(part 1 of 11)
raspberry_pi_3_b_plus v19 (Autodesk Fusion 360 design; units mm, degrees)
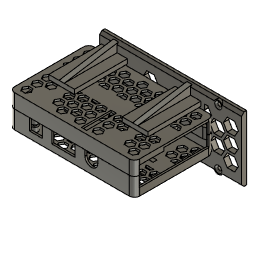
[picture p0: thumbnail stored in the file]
parameter "muc_width_int" = 6.9
parameter "muc_width_ext" = 7.5
parameter "muc_depth" = 5
parameter "muc_height_int" = 1.85
parameter "muc_height_ext" = 2.45
parameter "muc_shell_thickness" = 0.3
parameter "sdc_width" = 12
parameter "sdc_length" = 11.4
parameter "sdc_height" = 1.42
parameter "sdc_shell_thickness" = 0.15
parameter "h20x2_spacing" = 2.54
parameter "h20x2_pin_size" = 0.635
parameter "h20x2_pin_height" = 10
parameter "h20x2_pin_descent" = 3
parameter "h20x2_spacer_leg_size" = 0.5
parameter "h20x2_spacer_leg_height" = 0.5
parameter "h20x2_spacer_height" = 2.54
parameter "h20x2_spacer_taper" = 25
parameter "h20x2_spacer_break_depth" = 0.15
parameter "sop3_1_lead_thickness" = 0.1
parameter "sop3_1_lead_attach" = 0.3
parameter "sop3_1_lead_width" = 0.2
parameter "sop3_1_lead_spacing" = 0.5
parameter "sop3_1_package_width" = 1.6
parameter "sop3_1_package_height" = 0.6
parameter "sop3_1_package_depth" = 0.75
parameter "sop3_1_above_board" = 0.05
parameter "sop3_1_lead_extension" = 0.4
parameter "sop3_1_lead_foot_angle" = 5
parameter "sop3_1_lead_into_package" = 0.15
parameter "sop3_1_optional_lead_extension" = 0
parameter "cap0402_height" = 0.5
parameter "cap0402_width" = 0.5
parameter "cap0402_length" = 1
parameter "cap0402_tin_len" = 0.2
parameter "cap0402_tin_thick_radial" = 0.02
parameter "cap0402_tin_thick_axial" = 0.06
parameter "cap0402_land_spacing" = 0.5
parameter "cap0402_land_width" = 0.6
parameter "cap0402_land_length" = 0.5
parameter "cap0402_height_1" = 0.5
parameter "cap0402_width_1" = 0.5
parameter "cap0402_length_1" = 1
parameter "cap0402_tin_len_1" = 0.2
parameter "cap0402_tin_thick_radial_1" = 0.02
parameter "cap0402_tin_thick_axial_1" = 0.06
parameter "cap0402_land_spacing_1" = 0.5
parameter "cap0402_land_width_1" = 0.6
parameter "cap0402_land_length_1" = 0.5
parameter "h2x2_spacing" = 2.54
parameter "h2x2_pin_size" = 0.635
parameter "h2x2_pin_height" = 10
parameter "h2x2_pin_descent" = 3
parameter "h2x2_spacer_leg_size" = 0.5
parameter "h2x2_spacer_leg_height" = 0.5
parameter "h2x2_spacer_height" = 2.54
parameter "h2x2_spacer_taper" = 25
parameter "h2x2_spacer_break_depth" = 0.15
parameter "pj322_package_width" = 7
parameter "pj322_package_length" = 15
parameter "pj322_package_height" = 6
parameter "pj322_above_board" = 0.01
parameter "d372" = 0.5
canvas "Canvas1"
sketch "Sketch1" plane through (0, 0, 0) normal (0, 0, 1) x axis (1, 0, 0)
  line L1 (39.4, 28) -> (-39.4, 28)
  line L2 (39.4, 27.9) -> (39.4, 28)
  line L3 (42.5, 24.9) -> (42.4, 24.9)
  line L4 (42.5, -24.9) -> (42.5, 24.9)
  line L5 (42.4, -24.9) -> (42.5, -24.9)
  line L6 (39.4, -28) -> (39.4, -27.9)
  line L7 (-39.4, -28) -> (39.4, -28)
  line L8 (-39.4, -27.9) -> (-39.4, -28)
  line L9 (-42.5, -24.9) -> (-42.4, -24.9)
  line L10 (-42.5, 24.9) -> (-42.5, -24.9)
  line L11 (-42.4, 24.9) -> (-42.5, 24.9)
  line L12 (-39.4, 28) -> (-39.4, 27.9)
  line L13 (39.4, 24.9) -> (-39.4, -24.9)
  line L14 (39.4, -24.9) -> (-39.4, 24.9)
  line L15 (-17.625, -29.5) -> (-3.375, -29.5)
  line L16 (-17.625, -17.5) -> (-17.625, -29.5)
  line L17 (-3.375, -17.5) -> (-17.625, -17.5)
  line L18 (-3.375, -29.5) -> (-3.375, -17.5)
  line L19 (-17.625, -17.5) -> (-3.375, -29.5)
  line L20 (-3.375, -17.5) -> (-17.625, -29.5)
  line L21 (23.375, -25.5) -> (44.625, -25.5)
  line L22 (23.375, -10) -> (23.375, -25.5)
  line L23 (44.625, -10) -> (23.375, -10)
  line L24 (44.625, -25.5) -> (44.625, -10)
  line L25 (23.375, -10) -> (44.625, -25.5)
  line L26 (44.625, -10) -> (23.375, -25.5)
  line L27 (26.75, -5.625) -> (44.25, -5.625)
  line L28 (26.75, 7.625) -> (26.75, -5.625)
  line L29 (44.25, 7.625) -> (26.75, 7.625)
  line L30 (44.25, -5.625) -> (44.25, 7.625)
  line L31 (26.75, 7.625) -> (44.25, -5.625)
  line L32 (44.25, 7.625) -> (26.75, -5.625)
  line L33 (26.75, 12.375) -> (44.25, 12.375)
  line L34 (26.75, 25.625) -> (26.75, 12.375)
  line L35 (44.25, 25.625) -> (26.75, 25.625)
  line L36 (44.25, 12.375) -> (44.25, 25.625)
  line L37 (26.75, 25.625) -> (44.25, 12.375)
  line L38 (44.25, 25.625) -> (26.75, 12.375)
  line L39 (7.5, -27.75) -> (14.5, -27.75)
  line L40 (7.5, -15.75) -> (7.5, -27.75)
  line L41 (14.5, -15.75) -> (7.5, -15.75)
  line L42 (14.5, -27.75) -> (14.5, -15.75)
  line L43 (7.5, -15.75) -> (14.5, -27.75)
  line L44 (14.5, -15.75) -> (7.5, -27.75)
  line L45 (-35.65, -29.625) -> (-28.15, -29.625)
  line L46 (-35.65, -23.375) -> (-35.65, -29.625)
  line L47 (-28.15, -23.375) -> (-35.65, -23.375)
  line L48 (-28.15, -29.625) -> (-28.15, -23.375)
  line L49 (-35.65, -23.375) -> (-28.15, -29.625)
  line L50 (-28.15, -23.375) -> (-35.65, -29.625)
  line L51 (1, -27.625) -> (4, -27.625)
  line L52 (1, -5.375) -> (1, -27.625)
  line L53 (4, -5.375) -> (1, -5.375)
  line L54 (4, -27.625) -> (4, -5.375)
  line L55 (1, -5.375) -> (4, -27.625)
  line L56 (4, -5.375) -> (1, -27.625)
  line L57 (-40, -11.125) -> (-37, -11.125)
  line L58 (-40, 11.125) -> (-40, -11.125)
  line L59 (-37, 11.125) -> (-40, 11.125)
  line L60 (-37, -11.125) -> (-37, 11.125)
  line L61 (-40, 11.125) -> (-37, -11.125)
  line L62 (-37, 11.125) -> (-40, -11.125)
  line L63 (16.5, 16.127) -> (21.5, 16.127)
  line L64 (16.5, 20.627) -> (16.5, 16.127)
  line L65 (21.5, 20.627) -> (16.5, 20.627)
  line L66 (21.5, 16.127) -> (21.5, 20.627)
  line L67 (16.5, 20.627) -> (21.5, 16.127)
  line L68 (21.5, 20.627) -> (16.5, 16.127)
  line L69 (16.5, 11.01) -> (21.5, 11.01)
  line L70 (16.5, 13.01) -> (16.5, 11.01)
  line L71 (21.5, 13.01) -> (16.5, 13.01)
  line L72 (21.5, 11.01) -> (21.5, 13.01)
  line L73 (16.5, 13.01) -> (21.5, 11.01)
  line L74 (21.5, 13.01) -> (16.5, 11.01)
  line L75 (-35.5, 21.75) -> (15.5, 21.75)
  line L76 (-35.5, 26.75) -> (-35.5, 21.75)
  line L77 (15.5, 26.75) -> (-35.5, 26.75)
  line L78 (15.5, 21.75) -> (15.5, 26.75)
  line L79 (-35.5, 26.75) -> (15.5, 21.75)
  line L80 (15.5, 26.75) -> (-35.5, 21.75)
  line L81 (20.27, 12.01) -> (17.73, 12.01)
  line L82 (20.8, 18.377) -> (19, 18.377)
  line L83 (19, 20) -> (19, 18.377)
  arc A1 centre (39.4, 24.9) radius 3 clockwise from (39.4, 27.9) to (42.4, 24.9)
  arc A2 centre (39.4, -24.9) radius 3 clockwise from (42.4, -24.9) to (39.4, -27.9)
  arc A3 centre (-39.4, -24.9) radius 3 clockwise from (-39.4, -27.9) to (-42.4, -24.9)
  arc A4 centre (-39.4, 24.9) radius 3 clockwise from (-42.4, 24.9) to (-39.4, 27.9)
  circle C1 centre (-39, 24.5) radius 1.375
  circle C2 centre (19, 24.5) radius 1.375
  circle C3 centre (19, -24.5) radius 1.375
  circle C4 centre (-39, -24.5) radius 1.375
  circle C5 centre (17.73, 12.01) radius 0.5
  circle C6 centre (20.27, 12.01) radius 0.5
  circle C7 centre (17.73, 19.647) radius 0.5
  circle C8 centre (20.27, 19.647) radius 0.5
  circle C9 centre (20.27, 17.107) radius 0.5
  circle C10 centre (17.73, 17.107) radius 0.5
  circle C11 centre (-34.13, 22.98) radius 0.5
  circle C12 centre (-31.59, 22.98) radius 0.5
  circle C13 centre (-29.05, 22.98) radius 0.5
  circle C14 centre (-26.51, 22.98) radius 0.5
  circle C15 centre (-23.97, 22.98) radius 0.5
  circle C16 centre (-21.43, 22.98) radius 0.5
  circle C17 centre (-18.89, 22.98) radius 0.5
  circle C18 centre (-16.35, 22.98) radius 0.5
  circle C19 centre (-13.81, 22.98) radius 0.5
  circle C20 centre (-11.27, 22.98) radius 0.5
  circle C21 centre (-8.73, 22.98) radius 0.5
  circle C22 centre (-6.19, 22.98) radius 0.5
  circle C23 centre (-3.65, 22.98) radius 0.5
  circle C24 centre (-1.11, 22.98) radius 0.5
  circle C25 centre (1.43, 22.98) radius 0.5
  circle C26 centre (3.97, 22.98) radius 0.5
  circle C27 centre (6.51, 22.98) radius 0.5
  circle C28 centre (9.05, 22.98) radius 0.5
  circle C29 centre (11.59, 22.98) radius 0.5
  circle C30 centre (14.13, 22.98) radius 0.5
  circle C31 centre (-34.13, 25.52) radius 0.5
  circle C32 centre (-31.59, 25.52) radius 0.5
  circle C33 centre (-29.05, 25.52) radius 0.5
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  point P21 (-39.4, 24.9)
  point P6 (39.4, 24.9)
  point P11 (39.4, -24.9)
  point P15 (-39.4, -24.9)
  point P22 (-39.4, -24.9)
  point P23 (39.4, 24.9)
  point P24 (-39.4, 24.9)
  point P25 (39.4, -24.9)
  point P26 (0, 0)
  point P1 (0, 0)
  point P27 (-39, 24.5)
  point P30 (-39, -24.5)
  point P29 (19, -24.5)
  point P28 (19, 24.5)
  point P35 (-10.5, -23.5)
  point P40 (34, -17.75)
  point P45 (35.5, 1)
  point P50 (35.5, 19)
  point P55 (11, -21.75)
  point P60 (-31.9, -26.5)
  point P65 (2.5, -16.5)
  point P70 (-38.5, 0)
  point P75 (19, 18.377)
  point P80 (19, 12.01)
  point P85 (-10, 24.25)
  point P86 (17.73, 12.01)
  point P88 (17.73, 12.01)
  point P87 (20.27, 12.01)
  point P89 (20.27, 12.01)
  point P94 (19, 18.377)
  point P90 (17.73, 19.647)
  point P91 (20.27, 19.647)
  point P93 (17.73, 17.107)
  point P92 (20.27, 17.107)
  point P2 (-39.4, 28)
  point P20 (-39.4, 27.9)
  point P18 (-42.5, 24.9)
  point P19 (-42.4, 24.9)
  point P16 (-42.4, -24.9)
  point P17 (-42.5, -24.9)
  point P13 (-39.4, -28)
  point P14 (-39.4, -27.9)
  point P10 (39.4, -27.9)
  point P12 (39.4, -28)
  point P8 (42.5, -24.9)
  point P9 (42.4, -24.9)
  point P5 (42.4, 24.9)
  point P7 (42.5, 24.9)
  point P3 (39.4, 28)
  point P4 (39.4, 27.9)
  point P97 (-34.13, 22.98)
  horizontal L1
  vertical L12
  vertical L10
  horizontal L11
  coincident L11 P21
  coincident P21 L12
  vertical L2
  coincident L2 P6
  coincident P6 L3
  horizontal L3
  vertical L4
  horizontal L5
  vertical L6
  horizontal L7
  coincident P11 L6
  coincident L5 P11
  horizontal L9
  vertical L8
  coincident P15 L9
  coincident L8 P15
  equal A1 A4
  equal A3 A4
  equal A2 A3
  coincident P15 P22
  coincident P6 P23
  coincident P21 P24
  coincident P11 P25
  midpoint L13 P26
  coincident P1 P26
  equal C2 C3
  equal C2 C4
  equal C1 C4
  vertical P27 P30
  horizontal P29 P30
  vertical P28 P29
  horizontal P27 P28
  perpendicular L15 L16
  parallel L15 L17
  parallel L16 L18
  horizontal L15
  coincident L19 P35
  coincident L20 P35
  perpendicular L21 L22
  parallel L21 L23
  parallel L22 L24
  horizontal L21
  coincident L25 P40
  coincident L26 P40
  perpendicular L27 L28
  parallel L27 L29
  parallel L28 L30
  horizontal L27
  coincident L31 P45
  coincident L32 P45
  perpendicular L33 L34
  parallel L33 L35
  parallel L34 L36
  horizontal L33
  coincident L37 P50
  coincident L38 P50
  perpendicular L39 L40
  parallel L39 L41
  parallel L40 L42
  horizontal L39
  coincident L43 P55
  coincident L44 P55
  perpendicular L45 L46
  parallel L45 L47
  parallel L46 L48
  horizontal L45
  coincident L49 P60
  coincident L50 P60
  perpendicular L51 L52
  parallel L51 L53
  parallel L52 L54
  horizontal L51
  coincident L55 P65
  coincident L56 P65
  perpendicular L57 L58
  parallel L57 L59
  parallel L58 L60
  horizontal L57
  coincident L61 P70
  coincident L62 P70
  perpendicular L63 L64
  parallel L63 L65
  parallel L64 L66
  horizontal L63
  coincident L67 P75
  coincident L68 P75
  perpendicular L69 L70
  parallel L69 L71
  parallel L70 L72
  horizontal L69
  coincident L73 P80
  coincident L74 P80
  perpendicular L75 L76
  parallel L75 L77
  parallel L76 L78
  horizontal L75
  coincident L79 P85
  coincident L80 P85
  vertical P28 P75
  vertical P28 P80
  horizontal L81
  midpoint P80 L81
  coincident P86 P88
  coincident P87 P89
  equal C5 C6
  equal C7 C10
  equal C9 C10
  equal C8 C9
  coincident P75 P94
  horizontal L82
  perpendicular L82 L83
  symmetric P90 P91 L83
  symmetric P90 P93 L82
  symmetric P91 P92 L82
  dimension "d1" distance P2 P20 = 0.1
  dimension "d2" distance P18 P19 = 0.1 (= "d1")
  dimension "d3" distance P16 P17 = 0.1 (= "d1")
  dimension "d4" distance P13 P14 = 0.1 (= "d1")
  dimension "d5" distance P10 P12 = 0.1 (= "d1")
  dimension "d6" distance P8 P9 = 0.1 (= "d1")
  dimension "d7" distance P5 P7 = 0.1 (= "d1")
  dimension "d8" distance P3 P4 = 0.1 (= "d1")
  dimension "d9" radius A1 = 3
  dimension "d10" distance L4 L10 = 85
  dimension "d11" distance L1 L7 = 56
  dimension "d12" distance L10 P27 = 3.5
  dimension "d13" distance L1 P27 = 3.5
  dimension "d14" diameter C1 = 2.75
  dimension "d15" distance P27 P28 = 58
  dimension "d16" distance P27 P30 = 49
  dimension "d17" distance L10 P35 = 32
  dimension "d18" distance L16 L18 = 14.25
  dimension "d19" distance L15 L17 = 12
  dimension "d20" distance L7 P35 = 4.5
  dimension "d21" distance L7 P40 = 10.25
  dimension "d22" distance L21 L23 = 15.5
  dimension "d23" distance L22 L24 = 21.25
  dimension "d24" distance L4 P40 = 8.5
  dimension "d25" distance L7 P45 = 29
  dimension "d26" distance L27 L29 = 13.25
  dimension "d27" distance L28 L30 = 17.5
  dimension "d28" distance L4 P45 = 7
  dimension "d29" distance L33 L35 = 13.25 (= "d26")
  dimension "d30" distance L34 L36 = 17.5 (= "d27")
  dimension "d31" distance L7 P50 = 47
  dimension "d32" distance L4 P50 = 7 (= "d28")
  dimension "d33" distance L40 L42 = 7
  dimension "d34" distance L39 L41 = 12
  dimension "d35" distance L10 P55 = 53.5
  dimension "d36" distance L7 P55 = 6.25
  dimension "d37" distance L46 L48 = 7.5
  dimension "d38" distance L45 L47 = 6.25
  dimension "d39" distance L10 P60 = 10.6
  dimension "d40" distance L7 P60 = 1.5
  dimension "d41" distance L7 P65 = 11.5
  dimension "d42" distance P35 P65 = 13
  dimension "d43" distance L52 L54 = 3
  dimension "d44" distance L51 L53 = 22.25
  dimension "d45" distance L7 P70 = 28
  dimension "d46" distance L10 P70 = 4
  dimension "d47" distance P27 P85 = 29
  dimension "d48" distance L75 L77 = 5
  dimension "d49" distance L76 L78 = 51
  dimension "d50" distance L1 P85 = 3.75
  dimension "d51" distance L1 P75 = 9.623
  dimension "d52" distance L1 P80 = 15.99
  dimension "d53" distance L64 L66 = 5
  dimension "d54" distance L63 L65 = 4.5
  dimension "d55" distance L69 L71 = 2
  dimension "d56" distance L70 L72 = 5
  dimension "d57" distance L57 L59 = 22.25 (= "d44")
  dimension "d58" distance L58 L60 = 3 (= "d43")
  dimension "d61" diameter C6 = 1
  dimension "d62" distance P88 P89 = 2.54
  dimension "d63" diameter C7 = 1
  dimension "d64" distance P91 P92 = 2.54
  dimension "d65" distance P92 P93 = 2.54
  dimension "d66" diameter C11 = 1
  dimension "d72" distance P85 P97 = 24.13 (= "( d67 - 1 ) * d69 / 2")
  dimension "d73" distance P85 P97 = 1.27 (= "d70 / 2")
  dimension "d424" distance P7 = 1.5
  dimension "d69" R-Pattern1-uDistance = 2.54
  dimension "d70" R-Pattern1-vDistance = 2.54
  dimension "d7_1" Thickness = 0.3
  dimension "d230" Thickness = 0.15
  dimension "d238" Thickness = 0.08
  dimension "d87_1" Thickness = 0.15
  dimension "d261" Thickness = 0.2
  dimension "d1_3" Thickness = 0.3
  dimension "d1_4" Thickness = 0.3
  dimension "d1_5" Thickness = 0.15
  dimension "d46_6" angle = 22
  dimension "d119_2" Thickness = 0.35
  dimension "d159_4" Thickness = 0.2
  dimension "d1_6" Thickness = 0.5
extrude "Extrude1" new body sketch "Sketch1" along normal blind 1.6
decal "Decal1"
decal "Decal2"
work_plane "WorkPlane1" AlongDistance 2.15 (= "muc_height_int + muc_shell_thickness") named "d8_1"
sketch "Sketch1" plane through (0, 0, 2.15) normal (0, 0, 1) x axis (1, 0, 0)
  line L1 (-1.4, -1.4) -> (-1.4, 1.4)
  line L2 (2.28, 2.775) -> (2.03, 2.775)
  line L3 (-0.55, 2.9) -> (-1.4, 2.9)
  line L4 (-1.4, 2.9) -> (-1.4, 2.8)
  line L5 (-2, 3.45) -> (3, 3.45)
  line L6 (-2, 2.8) -> (-2, 3.45)
  line L7 (3, 3.45) -> (3, -3.45)
  line L8 (-1.4, 2.8) -> (-2, 2.8)
  line L9 (-0.55, 1.4) -> (-0.55, 2.9)
  line L10 (-1.4, 1.4) -> (-0.55, 1.4)
  line L11 (1.53, 2.925) -> (1.53, 2.775)
  line L12 (2.03, 2.775) -> (2.03, 2.925)
  line L13 (0.58, 2.775) -> (0.58, 1.975)
  line L14 (2.03, 2.925) -> (1.53, 2.925)
  line L15 (2.03, 1.975) -> (2.28, 1.975)
  line L16 (2.03, 1.825) -> (2.03, 1.975)
  line L17 (0.58, 1.975) -> (1.53, 1.975)
  line L18 (1.53, 1.975) -> (1.53, 1.825)
  line L19 (1.53, 2.775) -> (0.58, 2.775)
  line L20 (1.53, 1.825) -> (2.03, 1.825)
  line L21 (3, 0) -> (0, 0)
  line L22 (2.28, 1.975) -> (2.28, 2.775)
  line L23 (0.58, 2.375) -> (2.28, 2.375)
  line L24 (1.53, -2.775) -> (0.58, -2.775)
  line L25 (1.53, -2.925) -> (1.53, -2.775)
  line L26 (2.03, -2.925) -> (1.53, -2.925)
  line L27 (2.03, -2.775) -> (2.03, -2.925)
  line L28 (2.28, -2.775) -> (2.03, -2.775)
  line L29 (2.28, -1.975) -> (2.28, -2.775)
  line L30 (2.03, -1.975) -> (2.28, -1.975)
  line L31 (2.03, -1.825) -> (2.03, -1.975)
  line L32 (1.53, -1.825) -> (2.03, -1.825)
  line L33 (1.53, -1.975) -> (1.53, -1.825)
  line L34 (0.58, -1.975) -> (1.53, -1.975)
  line L35 (0.58, -2.775) -> (0.58, -1.975)
  line L36 (2.28, -2.375) -> (0.58, -2.375)
  line L37 (-1.4, -2.8) -> (-2, -2.8)
  line L38 (-1.4, -2.9) -> (-1.4, -2.8)
  line L39 (-0.55, -2.9) -> (-1.4, -2.9)
  line L40 (-0.55, -1.4) -> (-0.55, -2.9)
  line L41 (-1.4, -1.4) -> (-0.55, -1.4)
  line L42 (-2, -2.8) -> (-2, -3.45)
  line L43 (-2, -3.45) -> (3, -3.45)
  point P1 (0, 0)
  point P2 (0, 0)
  point P26 (0, 0)
  point P27 (3, 0)
  point P21 (3, 3.45)
  point P24 (3, 3.45)
  point P28 (2.28, 2.375)
  point P29 (0.58, 2.375)
  point P10 (1.53, 1.975)
  point P13 (1.53, 2.775)
  point P3 (2.03, 1.825)
  point P4 (2.03, 2.925)
  point P38 (2.03, -1.825)
  point P33 (2.03, -2.925)
  point P5 (2.03, 1.975)
  point P37 (2.03, -1.975)
  point P6 (0.58, 1.975)
  point P41 (0.58, -1.975)
  point P7 (1.53, 2.925)
  point P32 (1.53, -2.925)
  point P8 (2.28, 1.975)
  point P36 (2.28, -1.975)
  point P9 (1.53, 1.825)
  point P39 (1.53, -1.825)
  point P40 (1.53, -1.975)
  point P11 (0.58, 2.775)
  point P30 (0.58, -2.775)
  point P12 (2.28, 2.775)
  point P35 (2.28, -2.775)
  point P31 (1.53, -2.775)
  point P14 (2.03, 2.775)
  point P34 (2.03, -2.775)
  point P42 (0.58, -2.375)
  point P43 (2.28, -2.375)
  point P18 (-2, 2.8)
  point P25 (-2, 2.8)
  point P15 (-0.55, 1.4)
  point P48 (-0.55, -1.4)
  point P16 (-2, 3.45)
  point P50 (-2, -3.45)
  point P17 (-1.4, 1.4)
  point P49 (-1.4, -1.4)
  point P44 (-2, -2.8)
  point P19 (-1.4, 2.9)
  point P46 (-1.4, -2.9)
  point P20 (-1.4, 2.8)
  point P45 (-1.4, -2.8)
  point P52 (3, -3.45)
  point P22 (-0.55, 2.9)
  point P47 (-0.55, -2.9)
  point P51 (-2, -2.8)
  point P23 (3, -3.45)
  coincident P1 P2
  coincident P2 P26
  midpoint L7 P27
  horizontal L21
  horizontal L20
  vertical L16
  vertical L7
  horizontal L5
  coincident P21 P24
  midpoint L22 P28
  midpoint L13 P29
  horizontal L23
  horizontal L17
  vertical L13
  horizontal L19
  horizontal L14
  vertical L22
  horizontal L15
  vertical L18
  vertical L11
  vertical L12
  horizontal L2
  symmetric L14 L20 L23
  symmetric P10 P13 L23
  collinear L2 L19
  symmetric P3 P4 L23
  symmetric P3 L21 P38
  symmetric P4 L21 P33
  symmetric P5 L21 P37
  symmetric P6 L21 P41
  symmetric P7 L21 P32
  symmetric P8 L21 P36
  symmetric P9 L21 P39
  symmetric P10 L21 P40
  symmetric P11 L21 P30
  symmetric P12 L21 P35
  symmetric P13 L21 P31
  symmetric P14 L21 P34
  midpoint L35 P42
  midpoint L29 P43
  horizontal L8
  vertical L6
  vertical L4
  horizontal L3
  vertical L9
  horizontal L10
  vertical L1
  coincident P18 P25
  symmetric P15 L21 P48
  symmetric P16 L21 P50
  symmetric P17 L21 P49
  symmetric P18 L21 P44
  symmetric P19 L21 P46
  symmetric P20 L21 P45
  symmetric P21 L21 P52
  symmetric P22 L21 P47
  symmetric P25 L21 P51
  coincident P23 P52
  collinear L1 L4
  dimension "d11_1" distance L17 L19 = 0.8
  dimension "d13_1" distance L14 L19 = 0.15
  dimension "d14_1" distance P2 L13 = 0.58
  dimension "d15_1" distance P11 P13 = 0.95
  dimension "d16_1" distance P4 P7 = 0.5
  dimension "d17_1" distance P12 P14 = 0.25
  dimension "d18_1" distance P2 L7 = 3
  dimension "d19_1" distance L3 L8 = 0.1
  dimension "d20_1" distance L4 L9 = 0.85
  dimension "d21_1" distance L3 L5 = 0.55
  dimension "d22_1" distance L4 L6 = 0.6
  dimension "d23_1" distance L6 L7 = 5 (= "muc_depth")
  dimension "d24_1" distance L10 L41 = 2.8
  dimension "d25_1" distance L23 L36 = 4.75
  dimension "d26_1" distance L5 L43 = 6.9 (= "muc_width_int")
face "Face1" sketch "Sketch1"
face "EdgeFlange2" FlangeHeight 1.1429 (= "1 mm + muc_shell_thickness / 2 - 0.0071 mm") named "d27_1" FlangeAngle 90 named "d28_1"
face "EdgeFlange3" FlangeHeight 1 named "d29_1" FlangeAngle 45 named "d30_1"
face "EdgeFlange4" FlangeHeight 2.74 named "d31_1" FlangeAngle 45 named "d32_1"
step "Unfold1"
sketch "Sketch2" plane through (0, 0, 2.45) normal (0, 0, 1) x axis (1, 0, 0)
  line L1 (-2, -5.9396) -> (3, -5.9396)
  line L2 (-2, -8.5553) -> (-2, -5.9396)
  line L3 (3, -8.5553) -> (-2, -8.5553)
  line L4 (3, -5.9396) -> (3, -8.5553)
  line L5 (1, -10.8011) -> (1, -8.5553)
  line L6 (1.5, -9.5553) -> (0.5, -9.5553)
  line L7 (0.45, -8.9553) -> (0.3, -9.1553)
  line L8 (1.55, -8.9553) -> (1.7, -9.1553)
  line L9 (0.25, -9.4) -> (0.25, -9.027)
  line L10 (5.004, 0) -> (0, 0)
  line L11 (0.45, 8.1653) -> (0.3, 7.9653)
  line L12 (1.5, 7.5653) -> (0.5, 7.5653)
  line L13 (1.55, 8.1653) -> (1.7, 7.9653)
  line L14 (-2, 8.5553) -> (3, 8.5553)
  line L15 (1, 7.3491) -> (1, 8.5553)
  line L16 (1.75, 8.5653) -> (0.25, 8.5653)
  line L17 (0.25, 7.7235) -> (0.25, 8.5653)
  line L18 (-0.5, 6.6453) -> (-0.5, 8.5553)
  line L19 (-1.75, 6.6453) -> (-0.5, 6.6453)
  line L20 (3, 5.6097) -> (-2, 5.6097)
  line L21 (-2, 5.6097) -> (3, 5.6097)
  line L22 (-1.75, 5.6097) -> (-1.75, 6.6453)
  line L23 (-2, 5.9396) -> (-2, 8.5553)
  line L24 (-2, 5.6097) -> (-2, 5.9396)
  line L25 (-0.5, -6.6453) -> (-0.5, -8.5553)
  line L26 (-1.75, -6.6453) -> (-0.5, -6.6453)
  line L27 (-1.75, -5.6097) -> (-1.75, -6.6453)
  line L28 (3, -5.6097) -> (-2, -5.6097)
  line L29 (-2, -5.9396) -> (-2, -5.6097)
  line L30 (1.558, 8.1713) -> (1.708, 7.9713)
  line L31 (1.5, 7.5553) -> (0.5, 7.5553)
  line L32 (0.442, 8.1713) -> (0.292, 7.9713)
  arc A1 centre (0.5, -9.3053) radius 0.25 clockwise from (0.5, -9.5553) to (0.3, -9.1553)
  arc A2 centre (0.25, -8.8053) radius 0.25 clockwise from (0.25, -8.5553) to (0.45, -8.9553)
  arc A3 centre (1.5, -9.3053) radius 0.25 clockwise from (1.7, -9.1553) to (1.5, -9.5553)
  arc A4 centre (1.75, -8.8053) radius 0.25 clockwise from (1.55, -8.9553) to (1.75, -8.5553)
  arc A5 centre (0.25, 8.3153) radius 0.25 clockwise from (0.25, 8.5653) to (0.45, 8.1653)
  arc A6 centre (0.5, 7.8153) radius 0.25 clockwise from (0.5, 7.5653) to (0.3, 7.9653)
  arc A7 centre (1.5, 7.8153) radius 0.25 clockwise from (1.7, 7.9653) to (1.5, 7.5653)
  arc A8 centre (1.75, 8.3153) radius 0.25 clockwise from (1.55, 8.1653) to (1.75, 8.5653)
  arc A9 centre (1.75, 8.3153) radius 0.24 clockwise from (1.558, 8.1713) to (1.75, 8.5553)
  arc A10 centre (1.5, 7.8153) radius 0.26 clockwise from (1.708, 7.9713) to (1.5, 7.5553)
  arc A11 centre (0.5, 7.8153) radius 0.26 clockwise from (0.5, 7.5553) to (0.292, 7.9713)
  arc A12 centre (0.25, 8.3153) radius 0.24 clockwise from (0.25, 8.5553) to (0.442, 8.1713)
  point P11 (0.25, -8.5553)
  point P8 (0.5, -9.5553)
  point P16 (1.5, -9.5553)
  point P9 (0.3, -9.1553)
  point P15 (1.7, -9.1553)
  point P19 (1.75, -8.5553)
  point P13 (0.45, -8.9553)
  point P17 (1.55, -8.9553)
  point P29 (0.5, 7.5653)
  point P30 (1.5, 7.5653)
  point P26 (0.25, 8.5653)
  point P35 (1.75, 8.5653)
  point P49 (-0.5, 8.5553)
  point P56 (-1.75, 5.6097)
  point P58 (-0.5, -8.5553)
  point P50 (-0.5, 6.6453)
  point P59 (-0.5, -6.6453)
  point P55 (-1.75, 6.6453)
  point P60 (-1.75, -6.6453)
  point P61 (-1.75, -5.6097)
  point P1 (0, 0)
  point P22 (0, 0)
  point P51 (-2, 5.6097)
  vertical L5
  horizontal L6
  tangent L6 A1
  tangent L3 A2
  coincident L3 P11
  symmetric L5 P8 P16
  tangent A1 L7
  equal A1 A2
  tangent A2 L7
  symmetric L5 P8 P16
  symmetric L5 P9 P15
  symmetric L5 A1 A3
  symmetric L5 P11 P19
  symmetric L5 A2 A4
  symmetric L5 P13 P17
  vertical L9
  tangent A1 L9
  horizontal L10
  vertical L15
  horizontal L12
  tangent A8 L16
  horizontal L16
  tangent A5 L16
  tangent A6 L12
  tangent L11 A6
  tangent A5 L11
  tangent L13 A8
  tangent A7 L13
  tangent L12 A7
  symmetric P29 P30 L15
  symmetric P26 P35 L15
  equal A7 A8
  equal A5 A8
  equal A5 A6
  vertical L17
  tangent A6 L17
  coincident L14 P49
  perpendicular L14 L18
  coincident L20 P56
  vertical L22
  symmetric L10 P49 P58
  symmetric L10 P50 P59
  symmetric L10 P55 P60
  symmetric L10 P56 P61
  coincident P1 P22
  collinear L5 L15
  dimension "d33_1" distance L3 L6 = 1
  dimension "d35_1" distance L5 L9 = 0.75 (= "( 1.5 / 2 ) * 1 mm")
  dimension "d36_1" radius A1 = 0.25
  dimension "d37_1" distance P11 P19 = 1.5
  dimension "d44_1" radius A6 = 0.25
  dimension "d45_1" distance L14 L16 = 0.01
  dimension "d46_1" distance L12 L16 = 1
  dimension "d47_1" distance P26 P35 = 1.5
  dimension "d48_1" = 0.01
  dimension "d71" distance L14 L19 = 1.91 (= "( 3.82 / 2 ) * 1 mm")
  dimension "d72_1" distance P51 L22 = 0.25
  dimension "d73_1" distance L18 L23 = 1.5
  dimension "d166" distance P1 L5 = 1
extrude "Extrude1" cut sketch "Sketch2" profile of L14 L32 A10 A9 L30 L31 A11 A12 no distance stored
extrude "Extrude2" add sketch "Sketch2" profile of L3 L6 A1 A2 L7 A3 L8 A4 against normal blind 0.3 named "d50_1"
extrude "Extrude4" cut sketch "Sketch2" profile of L2 L3 L14 L18 L19 L20 L21 L22 L23 L24 L25 L26 L27 L28 L29 no distance stored
sketch "Sketch3" plane through (0, 0, 2.45) normal (0, 0, 1) x axis (1, 0, 0)
  line L1 (3, -5.6097) -> (-1.75, -5.6097)
  line L2 (3, -4.8582) -> (3, -5.6097)
  line L3 (-2, -4.8582) -> (3, -4.8582)
  line L4 (-2, -5.6097) -> (-2, -4.8582)
  line L5 (1.5, -4.1784) -> (1.5, -5.9396)
  line L6 (0.1, -4.1784) -> (1.5, -4.1784)
  line L7 (0.1, -5.9396) -> (0.1, -4.1784)
  line L8 (3, -4.5284) -> (-2, -4.5284)
  line L9 (0.8, -5.6097) -> (0.8, -4.1784)
  line L10 (3, 3.15) -> (3, -3.15)
  line L11 (5.3172, 0) -> (0, 0)
  line L12 (-1.75, -5.9396) -> (3, -5.9396)
  line L13 (3, 5.9396) -> (-1.75, 5.9396)
  line L14 (-1.75, -5.6097) -> (-2, -5.6097)
  line L15 (-0.48, -4.2284) -> (-0.48, -5.7396)
  line L16 (-1.55, -4.2284) -> (-0.48, -4.2284)
  line L17 (-1.55, -5.6097) -> (-1.55, -4.2284)
  line L18 (-1.75, -5.6097) -> (-1.55, -5.6097)
  line L19 (-1.75, -5.9396) -> (-1.75, -5.6097)
  line L20 (0.1, -5.9396) -> (1.5, -5.9396)
  line L21 (-1.1, -5.9396) -> (-0.7, -5.9396)
  line L22 (-1.75, -5.9396) -> (-1.1192, -5.9396)
  line L23 (0.1, 5.9396) -> (0.1, 4.1784)
  line L24 (0.1, 5.9396) -> (1.5, 5.9396)
  line L25 (1.5, 4.1784) -> (1.5, 5.9396)
  line L26 (0.1, 4.1784) -> (1.5, 4.1784)
  line L27 (-1.75, 5.9396) -> (-1.1192, 5.9396)
  line L28 (-1.1, 5.9396) -> (-0.7, 5.9396)
  line L29 (-1.55, 4.2284) -> (-0.48, 4.2284)
  line L30 (-1.55, 5.6097) -> (-1.55, 4.2284)
  line L31 (-1.75, 5.6097) -> (-1.55, 5.6097)
  line L32 (-1.75, 5.9396) -> (-1.75, 5.6097)
  line L33 (-0.48, 4.2284) -> (-0.48, 5.7396)
  arc A1 centre (-0.68, -5.7396) radius 0.2 clockwise from (-0.48, -5.7396) to (-0.68, -5.9396)
  arc A2 centre (-0.69, -5.94) radius 0.01 clockwise from (-0.68, -5.9396) to (-0.7, -5.9396)
  arc A3 centre (-1.1096, -5.9368) radius 0.01 clockwise from (-1.1, -5.9396) to (-1.1192, -5.9396)
  arc A4 centre (-1.1096, 5.9368) radius 0.01 clockwise from (-1.1192, 5.9396) to (-1.1, 5.9396)
  arc A5 centre (-0.69, 5.94) radius 0.01 clockwise from (-0.7, 5.9396) to (-0.68, 5.9396)
  arc A6 centre (-0.68, 5.7396) radius 0.2 clockwise from (-0.68, 5.9396) to (-0.48, 5.7396)
  point P12 (0.8, -4.1784)
  point P13 (0.8, -5.6097)
  point P1 (0, 0)
  point P16 (0, 0)
  point P9 (0.1, -5.9396)
  point P26 (-0.68, -5.9396)
  point P28 (-1.55, -5.6097)
  point P2 (-1.75, -5.6097)
  point P29 (-1.75, -5.6097)
  point P19 (-1.75, -5.9396)
  point P30 (-1.75, -5.9396)
  point P31 (-0.7, -5.9396)
  point P32 (-1.1, -5.9396)
  point P33 (-1.1192, -5.9396)
  point P34 (-1.75, -5.9396)
  point P6 (1.5, -5.9396)
  point P39 (1.5, 5.9396)
  point P7 (1.5, -4.1784)
  point P40 (1.5, 4.1784)
  point P8 (0.1, -4.1784)
  point P37 (0.1, 4.1784)
  point P38 (0.1, 5.9396)
  point P23 (-0.48, -5.7396)
  point P49 (-0.48, 5.7396)
  point P24 (-0.48, -4.2284)
  point P50 (-0.48, 4.2284)
  point P25 (-1.55, -4.2284)
  point P51 (-1.55, 4.2284)
  point P47 (-0.68, 5.9396)
  point P52 (-1.55, 5.6097)
  point P53 (-1.75, 5.6097)
  point P54 (-1.75, 5.9396)
  point P45 (-0.7, 5.9396)
  point P44 (-1.1, 5.9396)
  point P41 (-1.1192, 5.9396)
  point P42 (-1.75, 5.9396)
  point P22 (-2, -5.6097)
  vertical L5
  horizontal L6
  vertical L7
  midpoint L6 P12
  coincident L1 P13
  vertical L9
  coincident P1 P16
  horizontal L11
  coincident P9 L12
  vertical L15
  horizontal L16
  vertical L17
  coincident L12 P26
  tangent L15 A1
  coincident L1 P28
  coincident P2 P29
  coincident P19 P30
  coincident L12 P31
  horizontal L20
  coincident L12 P32
  coincident L12 P33
  coincident P19 P34
  equal A2 A3
  tangent L12 A1
  symmetric P6 L11 P39
  symmetric P7 L11 P40
  symmetric P8 L11 P37
  symmetric P9 L11 P38
  symmetric L11 P23 P49
  symmetric L11 P24 P50
  symmetric L11 P25 P51
  symmetric L11 P26 P47
  symmetric L11 A1 A6
  symmetric L11 P28 P52
  symmetric L11 P29 P53
  symmetric L11 P30 P54
  symmetric L11 P31 P45
  symmetric L11 P32 P44
  symmetric L11 P33 P41
  symmetric L11 P34 P42
  symmetric L11 A2 A5
  symmetric L11 A3 A4
  dimension "d52_1" distance L6 L8 = 0.35
  dimension "d53_1" distance L9 L10 = 2.2
  dimension "d54_1" distance L5 L7 = 1.4
  dimension "d79" distance L8 L16 = 0.3
  dimension "d81" radius A1 = 0.2
  dimension "d82" distance P22 L17 = 0.45
  dimension "d124" radius A2 = 0.01
  dimension "d125" distance P30 P31 = 1.05
  dimension "d126" distance P31 P32 = 0.4
extrude "Extrude3" cut sketch "Sketch3" profile of L5 L6 L7 L13 L15 L16 L17 A1 L18 L19 L20 L21 L22 A2 A3 L23 L24 L25 L26 L27 A4 L28 A5 A6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 no distance stored
step "Refold1"
face "EdgeFlange5" FlangeHeight 0.8 named "d63_1" FlangeAngle 90 named "d64_1" BendRadius 0.15 named "d65_1"
face "EdgeFlange8" FlangeHeight 0.5642 (= "( 0.62 mm - muc_shell_thickness / 4 ) / cos(d76)") FlangeAngle 15 named "d76"
face "EdgeFlange7" FlangeHeight 2.9362 (= "( 3 mm - muc_shell_thickness / 4 ) / sin(d70_1)") named "d69_1" FlangeAngle 85 named "d70_1"
face "EdgeFlange10" FlangeHeight 0.9 FlangeAngle 45
work_plane "WorkPlane2" AlongDistance 0.3
sketch "Sketch6" plane through (-0.85, 0, 0) normal (-1, 0, 0) x axis (0, 0, 1)
  line L1 (2.45, 2.7) -> (2.45, 2.9)
  line L2 (2.45, 1.6) -> (2.45, 1.4)
  line L3 (1.9297, 2.15) -> (2.45, 2.15)
  line L4 (2.45, 1.4) -> (2.45, 2.9)
  line L5 (2.45, 1.4) -> (2.15, 1.4)
  line L6 (2.45, 2.9) -> (2.15, 2.9)
  line L7 (2.15, 1.6) -> (2.15, 1.4)
  line L8 (2.15, 2.7) -> (2.15, 2.9)
  arc A1 centre (1.95, 2.7) radius 0.5 clockwise from (2.45, 2.7) to (2.2165, 2.2769)
  arc A2 centre (2.2964, 2.15) radius 0.15 clockwise from (2.2165, 2.0231) to (2.2165, 2.2769)
  arc A3 centre (1.95, 1.6) radius 0.5 clockwise from (2.2165, 2.0231) to (2.45, 1.6)
  arc A4 centre (1.95, 1.6) radius 0.2 clockwise from (2.0566, 1.7692) to (2.15, 1.6)
  arc A5 centre (2.2964, 2.15) radius 0.45 clockwise from (2.0566, 1.7692) to (2.0566, 2.5308)
  arc A6 centre (1.95, 2.7) radius 0.2 clockwise from (2.15, 2.7) to (2.0566, 2.5308)
  point P9 (2.45, 2.15)
  point P6 (2.2964, 2.15)
  point P12 (2.45, 1.4)
  point P13 (2.45, 1.4)
  point P2 (2.45, 2.7)
  point P11 (2.45, 2.9)
  point P14 (2.45, 2.9)
  point P21 (2.45, 1.4)
  point P22 (2.45, 2.9)
  tangent L1 A1
  tangent A1 A2
  tangent A2 A3
  horizontal L3
  vertical L1
  vertical L2
  tangent A3 L2
  midpoint P9 L4
  coincident P6 L3
  equal A1 A3
  coincident P12 P13
  coincident P2 L4
  coincident P11 P14
  coincident P12 P21
  perpendicular L2 L5
  coincident P11 P22
  perpendicular L1 L6
  dimension "d87" radius A2 = 0.15
  dimension "d89" distance P2 P14 = 0.2
  dimension "d90" radius A1 = 0.5
  dimension "d91" = 0.3
loft "Loft1" sketch "Sketch6"
mirror "Mirror1"
step "Unfold2"
sketch "Sketch7" plane through (0, 0, 2.45) normal (0, 0, 1) x axis (1, 0, 0)
  line L1 (-2.0231, -1.4) -> (-2.0231, 1.4)
  line L2 (-1.4, -1.4) -> (-2.0231, -1.4)
  line L3 (-1.4, 1.4) -> (-1.4, -1.4)
  line L4 (-2.0231, 1.4) -> (-1.4, 1.4)
  line L5 (-2.25, 0.875) -> (-1.45, 0.875)
  line L6 (-6.1503, 0) -> (0, 0)
  line L7 (-2.35, -0.775) -> (-2.35, 0.775)
  line L8 (-1.45, -0.875) -> (-2.25, -0.875)
  line L9 (-1.35, 0.775) -> (-1.35, -0.775)
  line L10 (-2.5, 1.8) -> (-2.5, 1.5)
  line L11 (-3.565, 2.5457) -> (-2.5, 1.8)
  line L12 (-4.6844, 2.6) -> (-3.7371, 2.6)
  line L13 (-4.6844, 2.25) -> (-4.6844, 2.6)
  line L14 (-4.0844, 2.25) -> (-4.6844, 2.25)
  line L15 (-3.2379, 1.4035) -> (-4.0844, 2.25)
  line L16 (-3.15, -1.1914) -> (-3.15, 1.1914)
  line L17 (-4.6844, 1.4) -> (-2.0231, 1.4)
  line L18 (-2.0231, -1.4) -> (-4.6844, -1.4)
  line L19 (-2.5, -1.8) -> (-2.5, -1.5)
  line L20 (-3.565, -2.5457) -> (-2.5, -1.8)
  line L21 (-4.6844, -2.6) -> (-3.7371, -2.6)
  line L22 (-4.6844, -2.25) -> (-4.6844, -2.6)
  line L23 (-4.0844, -2.25) -> (-4.6844, -2.25)
  line L24 (-3.2379, -1.4035) -> (-4.0844, -2.25)
  line L25 (-4.6844, -1.4) -> (-4.6844, 1.4)
  line L26 (3.5952, 5.9396) -> (3.5952, 8.5553)
  line L27 (3.5952, 8.5553) -> (3.5952, 5.9396)
  line L28 (3.3, 8.2553) -> (3.4452, 8.2553)
  line L29 (3.11, 8.5553) -> (3.5952, 8.5553)
  line L30 (3.5952, -8.5553) -> (3.5952, -5.9396)
  line L31 (3.5952, -5.9396) -> (3.5952, -8.5553)
  line L32 (3.3, -8.2553) -> (3.4452, -8.2553)
  line L33 (3.11, -8.5553) -> (3.5952, -8.5553)
  line L34 (3, -8.5553) -> (3.11, -8.5553)
  line L35 (3, 8.5553) -> (3.11, 8.5553)
  line L36 (3, 5.9396) -> (3, 8.5553)
  line L37 (3.5952, -8.5553) -> (3.11, -8.5553)
  line L38 (3.5952, -5.9396) -> (3.5952, -8.5553)
  line L39 (3.11, -5.9396) -> (3.5952, -5.9396)
  line L40 (3.5952, -3.8097) -> (3.5952, -4.5284)
  line L41 (3.11, -4.5284) -> (3.5952, -4.5284)
  line L42 (3.11, -3.8097) -> (3.5952, -3.8097)
  line L43 (3.11, -3.15) -> (3.5952, -3.15)
  line L44 (3.5952, 3.15) -> (3.5952, -3.15)
  line L45 (3.11, 3.15) -> (3.5952, 3.15)
  line L46 (3.11, 3.8097) -> (3.5952, 3.8097)
  line L47 (3.5952, 4.5284) -> (3.5952, 3.8097)
  line L48 (3.11, 4.5284) -> (3.5952, 4.5284)
  line L49 (3.11, 5.9396) -> (3.5952, 5.9396)
  line L50 (-1.4, 1.8187) -> (-2, 1.8187)
  line L51 (-2, 1.8187) -> (-1.4, 1.8187)
  line L52 (-1.9708, 2.3825) -> (-1.8916, 1.8187)
  line L53 (-2, 2.8) -> (-2, 3.15)
  line L54 (-2, 2.4701) -> (-2, 2.8)
  line L55 (-1.9708, -2.3825) -> (-1.8916, -1.8187)
  line L56 (-2, 1.8187) -> (-2, 2.4701)
  line L57 (-2, -2.4701) -> (-2, -1.8187)
  line L58 (-2, -1.8187) -> (-1.4, -1.8187)
  line L59 (-2, -2.8) -> (-2, -2.4701)
  arc A1 centre (-1.45, -0.775) radius 0.1 clockwise from (-1.35, -0.775) to (-1.45, -0.875)
  arc A2 centre (-1.45, 0.775) radius 0.1 clockwise from (-1.45, 0.875) to (-1.35, 0.775)
  arc A3 centre (-2.25, 0.775) radius 0.1 clockwise from (-2.35, 0.775) to (-2.25, 0.875)
  arc A4 centre (-2.25, -0.775) radius 0.1 clockwise from (-2.25, -0.875) to (-2.35, -0.775)
  arc A5 centre (-3.45, 1.1914) radius 0.3 clockwise from (-3.2379, 1.4035) to (-3.15, 1.1914)
  arc A6 centre (-2.4, 1.5) radius 0.1 clockwise from (-2.4, 1.4) to (-2.5, 1.5)
  arc A7 centre (-3.7371, 2.3) radius 0.3 clockwise from (-3.7371, 2.6) to (-3.565, 2.5457)
  arc A8 centre (-2.4, -1.5) radius 0.1 clockwise from (-2.5, -1.5) to (-2.4, -1.4)
  arc A9 centre (-3.7371, -2.3) radius 0.3 clockwise from (-3.565, -2.5457) to (-3.7371, -2.6)
  arc A10 centre (-3.45, -1.1914) radius 0.3 clockwise from (-3.15, -1.1914) to (-3.2379, -1.4035)
  arc A11 centre (3.3, 8.5553) radius 0.3 clockwise from (3.3, 8.2553) to (3, 8.5553)
  arc A12 centre (3.3, -8.5553) radius 0.3 clockwise from (3, -8.5553) to (3.3, -8.2553)
  arc A13 centre (3.4452, -8.1053) radius 0.15 clockwise from (3.5952, -8.1053) to (3.4452, -8.2553)
  arc A14 centre (3.4452, -6.0896) radius 0.15 clockwise from (3.4452, -5.9396) to (3.5952, -6.0896)
  arc A15 centre (3.4452, 6.0896) radius 0.15 clockwise from (3.5952, 6.0896) to (3.4452, 5.9396)
  arc A16 centre (3.4952, 4.4284) radius 0.1 clockwise from (3.4952, 4.5284) to (3.5952, 4.4284)
  arc A17 centre (3.4952, 3.9097) radius 0.1 clockwise from (3.5952, 3.9097) to (3.4952, 3.8097)
  arc A18 centre (3.4952, 3.05) radius 0.1 clockwise from (3.4952, 3.15) to (3.5952, 3.05)
  arc A19 centre (3.4452, 8.1053) radius 0.15 clockwise from (3.4452, 8.2553) to (3.5952, 8.1053)
  arc A20 centre (3.4952, -3.05) radius 0.1 clockwise from (3.5952, -3.05) to (3.4952, -3.15)
  arc A21 centre (3.4952, -3.9097) radius 0.1 clockwise from (3.4952, -3.8097) to (3.5952, -3.9097)
  arc A22 centre (3.4952, -4.4284) radius 0.1 clockwise from (3.5952, -4.4284) to (3.4952, -4.5284)
  arc A23 centre (1, 2.8) radius 3 clockwise from (-1.9708, 2.3825) to (-2, 2.8)
  arc A24 centre (1, -2.8) radius 3 clockwise from (-2, -2.8) to (-1.9708, -2.3825)
  point P1 (0, 0)
  point P6 (0, 0)
  point P28 (-2.4, 1.4)
  point P34 (-4.6844, 2.425)
  point P31 (-4.6844, 1.4)
  point P20 (-2.5, 1.5)
  point P39 (-2.5, -1.5)
  point P21 (-2.5, 1.8)
  point P41 (-2.5, -1.8)
  point P22 (-4.6844, 2.6)
  point P45 (-4.6844, -2.6)
  point P23 (-4.6844, 2.25)
  point P46 (-4.6844, -2.25)
  point P24 (-4.0844, 2.25)
  point P47 (-4.0844, -2.25)
  point P25 (-3.2379, 1.4035)
  point P48 (-3.2379, -1.4035)
  point P26 (-3.15, 1.1914)
  point P50 (-3.15, -1.1914)
  point P40 (-2.4, -1.4)
  point P35 (-3.565, 2.5457)
  point P42 (-3.565, -2.5457)
  point P36 (-3.7371, 2.6)
  point P44 (-3.7371, -2.6)
  point P51 (-4.6844, -2.425)
  point P58 (3, 8.5553)
  point P59 (3, 8.5553)
  point P68 (3, -8.5553)
  point P69 (3, -8.5553)
  point P76 (3.5952, -8.1053)
  point P83 (3.5952, -6.0896)
  point P82 (3.4452, -5.9396)
  point P98 (3.4452, 5.9396)
  point P97 (3.5952, 6.0896)
  point P102 (3.5952, 4.4284)
  point P101 (3.4952, 4.5284)
  point P105 (3.4952, 3.8097)
  point P104 (3.5952, 3.9097)
  point P108 (3.5952, 3.05)
  point P107 (3.4952, 3.15)
  point P110 (3.5952, 8.1053)
  point P113 (3.5952, -3.05)
  point P112 (3.4952, -3.15)
  point P116 (3.5952, -3.9097)
  point P115 (3.4952, -3.8097)
  point P119 (3.5952, -4.4284)
  point P118 (3.4952, -4.5284)
  point P125 (-1.8916, 1.8187)
  point P129 (-2, 2.8)
  point P128 (-2, 2.8)
  point P132 (-1.8916, -1.8187)
  point P126 (-1.9708, 2.3825)
  point P133 (-1.9708, -2.3825)
  point P135 (-2, -2.8)
  coincident P1 P6
  horizontal L6
  horizontal L5
  vertical L7
  horizontal L8
  tangent L8 A1
  tangent L9 A1
  tangent L5 A2
  tangent L9 A2
  equal A1 A2
  tangent L5 A3
  tangent L7 A3
  equal A1 A3
  tangent L7 A4
  tangent L8 A4
  equal A1 A4
  symmetric L5 L6 L8
  vertical L9
  tangent L15 A5
  vertical L16
  vertical L10
  tangent L10 A6
  coincident P28 L17
  tangent A6 L17
  horizontal L14
  horizontal L12
  vertical L13
  midpoint L13 P34
  vertical P31 P34
  tangent A5 L16
  tangent L11 A7
  tangent L12 A7
  symmetric L6 P20 P39
  symmetric L6 P21 P41
  symmetric L6 P22 P45
  symmetric L6 P23 P46
  symmetric L6 P24 P47
  symmetric L6 P25 P48
  symmetric L6 P26 P50
  symmetric L6 A5 A10
  symmetric L6 P28 P40
  symmetric L6 A6 A8
  symmetric L6 P35 P42
  symmetric L6 P36 P44
  symmetric L6 A7 A9
  midpoint L22 P51
  coincident P58 P59
  tangent L28 A11
  horizontal L28
  coincident P68 P69
  tangent L32 A12
  horizontal L32
  coincident L31 P76
  tangent L32 A13
  tangent L30 A13
  tangent L30 A14
  coincident L30 P83
  coincident L39 P82
  tangent L39 A14
  equal A13 A14
  tangent L26 A15
  coincident P98 L49
  coincident L26 P97
  tangent L47 A16
  coincident L47 P102
  coincident L48 P101
  tangent L46 A17
  coincident L46 P105
  coincident L47 P104
  tangent L44 A18
  coincident L44 P108
  coincident L45 P107
  tangent L26 A19
  coincident L26 P110
  tangent L44 A20
  coincident L44 P113
  coincident L43 P112
  tangent L40 A21
  coincident L40 P116
  coincident L42 P115
  tangent L40 A22
  coincident L40 P119
  coincident L41 P118
  tangent L41 A22
  tangent L42 A21
  tangent L43 A20
  tangent L45 A18
  tangent L47 A17
  tangent L48 A16
  tangent A15 L49
  tangent L28 A19
  equal A15 A19
  equal A16 A17
  equal A17 A18
  equal A18 A20
  equal A20 A21
  equal A21 A22
  coincident L50 P125
  tangent L52 A23
  coincident P129 L54
  tangent A23 L54
  coincident P128 P129
  symmetric L6 P125 P132
  symmetric L6 P126 P133
  symmetric L6 P129 P135
  symmetric L6 A23 A24
  dimension "d93" radius A1 = 0.1
  dimension "d94" distance P1 L9 = 1.35
  dimension "d95" distance L7 L9 = 1
  dimension "d96" distance L5 L8 = 1.75
  dimension "d98" distance L12 L14 = 0.35
  dimension "d99" distance P21 L17 = 0.4
  dimension "d100" angle L10 L11 = 55
  dimension "d101" radius A5 = 0.3
  dimension "d102" distance L10 L16 = 0.65
  dimension "d103" distance P1 L10 = 2.5
  dimension "d104" radius A6 = 0.1
  dimension "d105" angle L14 L15 = 135 (= "180 deg - 45 deg")
  dimension "d106" distance P23 P24 = 0.6
  dimension "d107" radius A7 = 0.3
  dimension "d108" distance P34 P51 = 4.85
  dimension "d113" distance L28 L29 = 0.3
  dimension "d114" radius A11 = 0.3
  dimension "d115" distance L32 L33 = 0.3
  dimension "d116" radius A12 = 0.3
  dimension "d117" radius A13 = 0.15
  dimension "d118" radius A19 = 0.15
  dimension "d119" radius A18 = 0.1
  dimension "d156" angle L52 L54 = 172
  dimension "d157" radius A23 = 3
extrude "Extrude5" cut sketch "Sketch7" profile of L5 L7 L8 L9 A1 A2 A3 A4 L16 L17 L18 L25 no distance stored
extrude "Extrude6" add sketch "Sketch7" profile of L10 L11 L12 L13 L14 L15 A5 L16 A6 L17 L18 A7 A8 L19 L20 A9 L21 L22 L23 L24 A10 no distance stored
extrude "Extrude7" cut sketch "Sketch7" profile of L26 L27 L28 A11 L29 L30 L31 L32 A12 L33 L34 L35 A13 L37 L38 L39 A14 L40 L41 L42 L43 L44 L45 L46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 no distance stored
step "Refold2"
chamfer "Chamfer1" distance 0.125
face "EdgeFlange11" FlangeHeight 0.13 FlangeAngle 45 BendRadius 0.01
face "EdgeFlange12" FlangeHeight 0.8 FlangeAngle 45 BendRadius 0.05
work_plane "WorkPlane1" AlongDistance -1.4 (= "-( 2 mm - 0.60 mm )")
sketch "Sketch1" plane through (-1.4, 0, 0) normal (1, 0, 0) x axis (0, 1, 0)
  line L1 (-3.125, 2.15) -> (3.125, 2.15)
  line L2 (-3.425, 0.6) -> (-3.425, 1.85)
  line L3 (3.125, 0.3) -> (-3.125, 0.3)
  line L4 (3.425, 1.85) -> (3.425, 0.6)
  line L5 (0, -3.75) -> (0, 0)
  arc A1 centre (-3.125, 0.6) radius 0.3 clockwise from (-3.125, 0.3) to (-3.425, 0.6)
  arc A2 centre (-3.125, 1.85) radius 0.3 clockwise from (-3.425, 1.85) to (-3.125, 2.15)
  arc A3 centre (3.125, 1.85) radius 0.3 clockwise from (3.125, 2.15) to (3.425, 1.85)
  arc A4 centre (3.125, 0.6) radius 0.3 clockwise from (3.425, 0.6) to (3.125, 0.3)
  point P1 (0, 0)
  point P2 (0, 0)
  horizontal L1
  vertical L2
  horizontal L3
  vertical L4
  coincident P1 P2
  vertical L5
  tangent L2 A1
  tangent L3 A1
  tangent L1 A2
  tangent L2 A2
  equal A1 A2
  tangent L1 A3
  tangent L4 A3
  equal A1 A3
  tangent L3 A4
  tangent L4 A4
  equal A1 A4
  symmetric L2 L4 L5
  dimension "d134" radius A1 = 0.3
  dimension "d135" distance L1 L3 = 1.85 (= "muc_height_int")
  dimension "d136" distance L2 L4 = 6.85 (= "muc_width_int - 0.05 mm")
  dimension "d137" distance P1 L3 = 0.3 (= "muc_shell_thickness")
extrude "Extrude1" new body sketch "Sketch1" profile of L1 L2 L3 L4 A1 A2 A3 A4 along normal blind 0.55
sketch "Sketch2" plane through (-1.4, 0, 0) normal (-1, 0, 0) x axis (0, 0, 1)
  line L1 (0.3, -3.125) -> (0.3, 3.125)
  line L2 (1.85, -3.425) -> (0.6, -3.425)
  line L3 (2.15, 3.125) -> (2.15, -3.125)
  line L4 (0.6, 3.425) -> (1.85, 3.425)
  line L5 (1.4, 1.975) -> (2.15, 2.725)
  line L6 (0.4, 2.6752) -> (1.4, 1.975)
  line L7 (0.9692, 3.3536) -> (0.4, 2.6752)
  line L8 (-1.2083, 0) -> (0, 0)
  line L9 (2.15, 1.225) -> (1.4, 1.975)
  line L10 (1.85, 3.425) -> (1.1224, 3.425)
  line L11 (0.4, -2.6752) -> (1.4, -1.975)
  line L12 (0.9692, -3.3536) -> (0.4, -2.6752)
  line L13 (1.85, -3.425) -> (1.1224, -3.425)
  line L14 (1.4, -1.975) -> (2.15, -2.725)
  line L15 (2.15, -1.225) -> (1.4, -1.975)
  arc A1 centre (0.6, 3.125) radius 0.3 clockwise from (0.3, 3.125) to (0.6, 3.425)
  arc A2 centre (0.6, -3.125) radius 0.3 clockwise from (0.6, -3.425) to (0.3, -3.125)
  arc A3 centre (1.85, -3.125) radius 0.3 clockwise from (2.15, -3.125) to (1.85, -3.425)
  arc A4 centre (1.85, 3.125) radius 0.3 clockwise from (1.85, 3.425) to (2.15, 3.125)
  arc A5 centre (1.1224, 3.225) radius 0.2 clockwise from (0.9692, 3.3536) to (1.1224, 3.425)
  arc A6 centre (1.1224, -3.225) radius 0.2 clockwise from (1.1224, -3.425) to (0.9692, -3.3536)
  point P14 (2.15, 2.725)
  point P1 (0, 0)
  point P17 (0, 0)
  point P19 (2.15, 1.225)
  point P12 (1.85, 3.425)
  point P20 (1.85, 3.425)
  point P30 (2.15, -2.725)
  point P15 (1.4, 1.975)
  point P24 (1.4, -1.975)
  point P16 (0.4, 2.6752)
  point P25 (0.4, -2.6752)
  point P31 (2.15, -1.225)
  point P29 (1.85, -3.425)
  point P21 (0.9692, 3.3536)
  point P26 (0.9692, -3.3536)
  point P22 (1.1224, 3.425)
  point P28 (1.1224, -3.425)
  coincident L3 P14
  coincident P1 P17
  horizontal L8
  perpendicular L5 L9
  coincident L3 P19
  coincident P12 P20
  tangent L7 A5
  tangent L10 A5
  horizontal L10
  symmetric P14 L8 P30
  symmetric P15 L8 P24
  symmetric P16 L8 P25
  symmetric L8 P19 P31
  symmetric L8 P20 P29
  symmetric L8 P21 P26
  symmetric L8 P22 P28
  symmetric L8 A5 A6
  dimension "d140" distance L4 P14 = 0.7
  dimension "d143" distance L3 P15 = 0.75
  dimension "d144" angle L3 L5 = 45
  dimension "d145" angle L5 L6 = 100
  dimension "d150" angle L4 L7 = 130
  dimension "d158" distance L1 P16 = 0.1
  dimension "d159" radius A5 = 0.2
extrude "Extrude2" add sketch "Sketch2" profile of L2 A3 L3 A4 L4 L5 L6 L7 L10 A5 L11 L12 A6 L13 L14 along normal blind 0.65
extrude "Extrude3" add sketch "Sketch2" profile of A1 L1 A2 L2 L3 L4 L6 L7 L9 A5 L11 L12 A6 L15 along normal blind 0.15
sketch "Sketch3" plane through (-0.85, 0, 0) normal (1, 0, 0) x axis (0, 0, -1)
  line L1 (-1.85, 3.425) -> (-0.6, 3.425)
  line L2 (-2.15, -3.125) -> (-2.15, 3.125)
  line L3 (-0.6, -3.425) -> (-1.85, -3.425)
  line L4 (-0.3, 3.125) -> (-0.3, -3.125)
  line L5 (-1.8, -2.4) -> (-2.15, -2.75)
  line L6 (-1.8, -1.9) -> (-1.8, -2.4)
  line L7 (-2.15, -1.55) -> (-1.8, -1.9)
  line L8 (-2.3524, 0) -> (0, 0)
  line L9 (-1.8, 2.4) -> (-2.15, 2.75)
  line L10 (-1.8, 1.9) -> (-1.8, 2.4)
  line L11 (-2.15, 1.55) -> (-1.8, 1.9)
  arc A1 centre (-0.6, 3.125) radius 0.3 clockwise from (-0.6, 3.425) to (-0.3, 3.125)
  arc A2 centre (-1.85, 3.125) radius 0.3 clockwise from (-2.15, 3.125) to (-1.85, 3.425)
  arc A3 centre (-1.85, -3.125) radius 0.3 clockwise from (-1.85, -3.425) to (-2.15, -3.125)
  arc A4 centre (-0.6, -3.125) radius 0.3 clockwise from (-0.3, -3.125) to (-0.6, -3.425)
  point P14 (-2.15, -2.75)
  point P17 (-2.15, -1.55)
  point P1 (0, 0)
  point P18 (0, 0)
  point P20 (-1.8, -2.15)
  point P22 (-2.15, 2.75)
  point P15 (-1.8, -2.4)
  point P23 (-1.8, 2.4)
  point P16 (-1.8, -1.9)
  point P24 (-1.8, 1.9)
  point P25 (-2.15, 1.55)
  point P21 (-1.8, 2.15)
  coincident L2 P14
  coincident L2 P17
  vertical L6
  coincident P1 P18
  horizontal L8
  midpoint L6 P20
  perpendicular L5 L7
  symmetric P14 L8 P22
  symmetric P15 L8 P23
  symmetric P16 L8 P24
  symmetric P17 L8 P25
  symmetric L8 P20 P21
  dimension "d160" distance L2 L6 = 0.35
  dimension "d161" angle L5 L6 = 135
  dimension "d162" distance P15 P16 = 0.5
  dimension "d163" distance P20 P21 = 4.3 (= "2.8 mm + 1.5 mm")
extrude "Extrude4" add sketch "Sketch3" profile of A1 L1 A2 L2 A3 L3 A4 L4 L5 L6 L7 L9 L10 L11 along normal blind 0.35
sketch "Sketch4" plane through (0, 0, 0.3) normal (0, 0, -1) x axis (-1, 0, 0)
  line L1 (0.5, 3.125) -> (1.55, 3.125)
  line L2 (0.5, -3.125) -> (0.5, 3.125)
  line L3 (1.55, -3.125) -> (0.5, -3.125)
  line L4 (1.55, 3.125) -> (1.55, -3.125)
  line L5 (0.7, 1.91) -> (1.55, 1.91)
  line L6 (0.5, -1.71) -> (0.5, 1.71)
  line L7 (1.55, -1.91) -> (0.7, -1.91)
  line L8 (1.55, 1.91) -> (1.55, -1.91)
  line L9 (2.601, 0) -> (0, 0)
  line L10 (0.7, -1.91) -> (0.5, -1.71)
  line L11 (0.7, 1.91) -> (0.5, 1.71)
  point P11 (1.55, -1.91)
  point P1 (0, 0)
  point P12 (0, 0)
  point P15 (0.5, 1.71)
  point P10 (1.55, -1.91)
  point P6 (1.55, 1.91)
  point P7 (1.55, 1.91)
  point P8 (0.7, 1.91)
  point P14 (0.7, -1.91)
  point P9 (0.5, -1.71)
  vertical L6
  horizontal L7
  vertical L8
  horizontal L5
  coincident L4 P11
  coincident P1 P12
  horizontal L9
  coincident L2 P15
  coincident P10 P11
  coincident P6 P7
  symmetric P8 L9 P14
  symmetric P9 L9 P15
  dimension "d168" distance L5 L7 = 3.82
  dimension "d170" angle L6 L10 = 45
  dimension "d171" distance P9 P14 = 0.2
extrude "Extrude5" add sketch "Sketch4" profile of L2 L4 L5 L6 L7 L8 L10 L11 along normal blind 0.3 (= "muc_shell_thickness")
